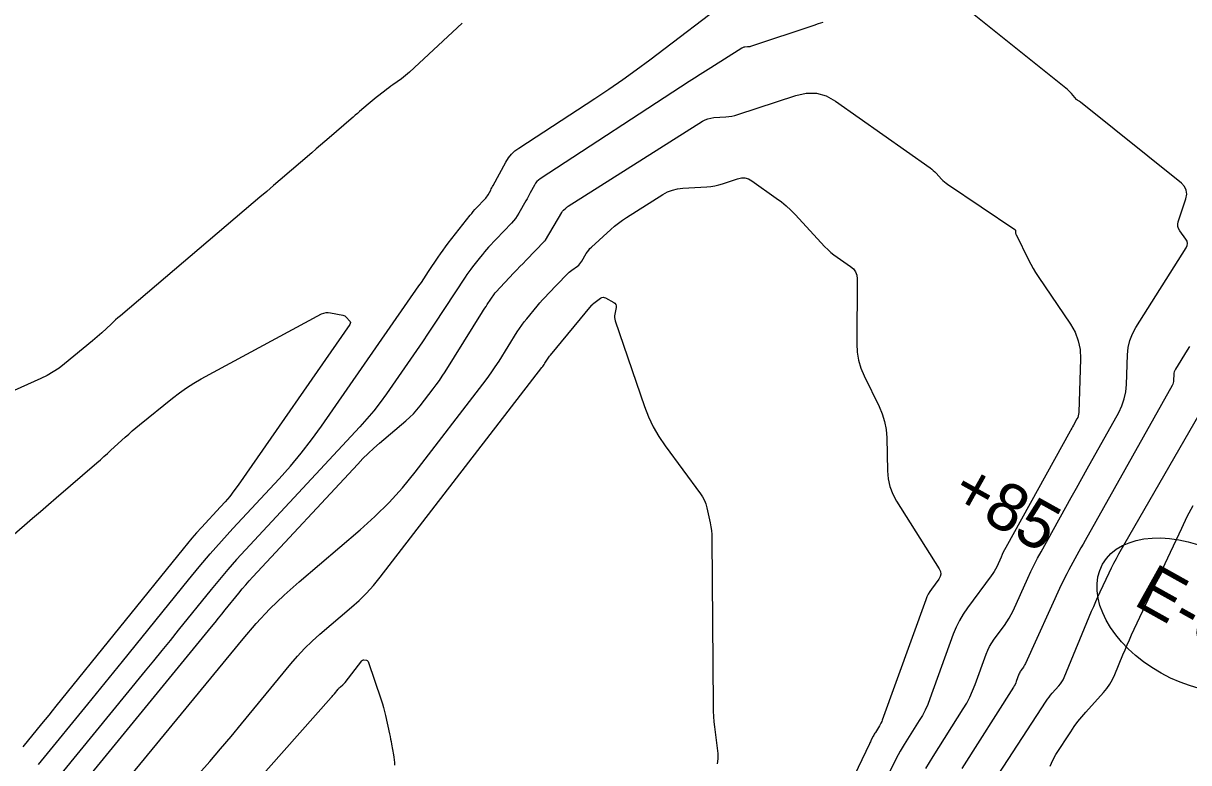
# Model space of a CAD drawing. Extents: x 1005228 to 1008882, y 1883389 to 1885754.
# Drawn here: x 1008141.6 to 1008294.8, y 1884868.6 to 1884965.9 of the extents above; entities that cross this region are included whole.
import ezdxf

# ---------------------------------------------------------------- set-up
doc = ezdxf.new("R2010")
doc.units = 0
for name, color, linetype in [('C-ANNO-NOTE', 7, 'Continuous'), ('R_Erosion', 7, 'Continuous'), ('S_BASELINE', 7, 'Continuous'), ('S_BRIDGE', 7, 'Continuous')]:
    doc.layers.add(name, color=color, linetype=linetype)

msp = doc.modelspace()

# ---------------------------------------------------------------- linework, layer by layer
at = {"layer": 'C-ANNO-NOTE'}
for points in [[(1008143.57, 1884868.4), (1008144, 1884868.89), (1008150.07, 1884876.31), (1008151.22, 1884877.72), (1008152.37, 1884879.13), (1008153.51, 1884880.54), (1008154.65, 1884881.95), (1008163.3, 1884892.66), (1008164.72, 1884894.38), (1008166.16, 1884896.08), (1008167.64, 1884897.76), (1008169.14, 1884899.4), (1008175.22, 1884905.95), (1008176.71, 1884907.61), (1008178.13, 1884909.32), (1008179.5, 1884911.07), (1008180.8, 1884912.88), (1008193.61, 1884931.32), (1008193.94, 1884931.79), (1008194.25, 1884932.26), (1008194.57, 1884932.73), (1008194.88, 1884933.2), (1008196.13, 1884935.09), (1008196.44, 1884935.56), (1008196.77, 1884936.03), (1008197.11, 1884936.48), (1008197.45, 1884936.93), (1008200.33, 1884940.61), (1008200.54, 1884940.86), (1008200.75, 1884941.11), (1008200.96, 1884941.35), (1008201.18, 1884941.59), (1008202.27, 1884942.73), (1008202.39, 1884942.86), (1008202.5, 1884943), (1008202.6, 1884943.15), (1008202.69, 1884943.3), (1008203.04, 1884943.92), (1008203.12, 1884944.07), (1008203.21, 1884944.23), (1008203.29, 1884944.38), (1008203.38, 1884944.54), (1008205.04, 1884947.61), (1008205.38, 1884948.15), (1008205.77, 1884948.64), (1008206.22, 1884949.07), (1008206.73, 1884949.45), (1008216.74, 1884955.98), (1008218.58, 1884957.21), (1008220.39, 1884958.46), (1008222.18, 1884959.75), (1008223.95, 1884961.07), (1008234.77, 1884969.32)], [(1008199.31, 1884965.87), (1008192.37, 1884959.44), (1008192.11, 1884959.21), (1008191.85, 1884958.99), (1008191.58, 1884958.77), (1008191.31, 1884958.57), (1008190.19, 1884957.77), (1008189.91, 1884957.57), (1008189.64, 1884957.36), (1008189.36, 1884957.15), (1008189.09, 1884956.95), (1008187.99, 1884956.09), (1008187.72, 1884955.87), (1008187.45, 1884955.66), (1008187.18, 1884955.44), (1008186.92, 1884955.21), (1008185.79, 1884954.24), (1008185.51, 1884954), (1008185.23, 1884953.76), (1008184.96, 1884953.52), (1008184.68, 1884953.28), (1008181.81, 1884950.81), (1008181.24, 1884950.32), (1008180.66, 1884949.83), (1008180.09, 1884949.34), (1008179.52, 1884948.84), (1008175.36, 1884945.27), (1008174.48, 1884944.51), (1008173.59, 1884943.75), (1008172.71, 1884942.99), (1008171.82, 1884942.24), (1008154.35, 1884927.39), (1008154.04, 1884927.12), (1008153.73, 1884926.85), (1008153.43, 1884926.58), (1008153.13, 1884926.3), (1008151.93, 1884925.17), (1008151.63, 1884924.89), (1008151.32, 1884924.62), (1008151.01, 1884924.35), (1008150.7, 1884924.09), (1008147.03, 1884921.08), (1008146.3, 1884920.51), (1008145.54, 1884920), (1008144.74, 1884919.55), (1008143.91, 1884919.14), (1008130.71, 1884913.22)], [(1008148.97, 1884865.29), (1008166.35, 1884886.51), (1008166.8, 1884887.06), (1008167.25, 1884887.61), (1008167.7, 1884888.16), (1008168.14, 1884888.71), (1008169.92, 1884890.92), (1008170.37, 1884891.47), (1008170.83, 1884892), (1008171.3, 1884892.54), (1008171.78, 1884893.06), (1008185.56, 1884907.89), (1008186.24, 1884908.61), (1008186.95, 1884909.3), (1008187.67, 1884909.97), (1008188.41, 1884910.63), (1008191.87, 1884913.57), (1008192.39, 1884914.04), (1008192.88, 1884914.52), (1008193.34, 1884915.03), (1008193.77, 1884915.57), (1008195.47, 1884917.77), (1008195.88, 1884918.32), (1008196.29, 1884918.88), (1008196.67, 1884919.46), (1008197.05, 1884920.04), (1008201.96, 1884927.89), (1008202.11, 1884928.13), (1008202.27, 1884928.38), (1008202.43, 1884928.62), (1008202.59, 1884928.87), (1008203.52, 1884930.28), (1008203.53, 1884930.3), (1008203.55, 1884930.32), (1008203.56, 1884930.34), (1008203.57, 1884930.36), (1008203.63, 1884930.44), (1008203.65, 1884930.46), (1008203.66, 1884930.48), (1008203.68, 1884930.49), (1008203.7, 1884930.51), (1008206.08, 1884933.02), (1008206.49, 1884933.44), (1008206.89, 1884933.86), (1008207.3, 1884934.28), (1008207.7, 1884934.71), (1008210.13, 1884937.22), (1008210.13, 1884937.23), (1008210.14, 1884937.24), (1008210.15, 1884937.25), (1008210.16, 1884937.26), (1008210.2, 1884937.29), (1008210.21, 1884937.29), (1008210.22, 1884937.3), (1008210.23, 1884937.31), (1008210.24, 1884937.32), (1008212.39, 1884940.99), (1008212.44, 1884941.07), (1008212.5, 1884941.15), (1008212.56, 1884941.22), (1008212.63, 1884941.29), (1008212.92, 1884941.55), (1008212.99, 1884941.62), (1008213.07, 1884941.68), (1008213.15, 1884941.73), (1008213.23, 1884941.79), (1008230.88, 1884952.97), (1008231.22, 1884953.16), (1008231.59, 1884953.3), (1008231.96, 1884953.4), (1008232.36, 1884953.45), (1008233.96, 1884953.54), (1008234.36, 1884953.58), (1008234.75, 1884953.64), (1008235.14, 1884953.73), (1008235.52, 1884953.84), (1008243.15, 1884956.38), (1008244.53, 1884956.68), (1008245.86, 1884956.65), (1008247.13, 1884956.3), (1008248.36, 1884955.61), (1008260.82, 1884946.83), (1008261.03, 1884946.67), (1008261.23, 1884946.51), (1008261.43, 1884946.33), (1008261.61, 1884946.14), (1008262.32, 1884945.37), (1008262.5, 1884945.18), (1008262.7, 1884945.01), (1008262.9, 1884944.84), (1008263.11, 1884944.69), (1008271.95, 1884938.73), (1008271.99, 1884938.69), (1008272.03, 1884938.65), (1008272.04, 1884938.6), (1008272.05, 1884938.54), (1008272.05, 1884938.3), (1008272.05, 1884938.24), (1008272.06, 1884938.18), (1008272.08, 1884938.12), (1008272.1, 1884938.07), (1008273.74, 1884934.74), (1008274.03, 1884934.17), (1008274.34, 1884933.62), (1008274.67, 1884933.07), (1008275.02, 1884932.54), (1008279.25, 1884926.3), (1008279.86, 1884925.24), (1008280.28, 1884924.12), (1008280.52, 1884922.95), (1008280.57, 1884921.73), (1008280.35, 1884914.68), (1008280.33, 1884914.45), (1008280.28, 1884914.24), (1008280.21, 1884914.02), (1008280.11, 1884913.82), (1008279.66, 1884913.02), (1008279.54, 1884912.81), (1008279.43, 1884912.61), (1008279.32, 1884912.41), (1008279.21, 1884912.21), (1008270.76, 1884896.91), (1008270.59, 1884896.6), (1008270.43, 1884896.29), (1008270.28, 1884895.98), (1008270.13, 1884895.67), (1008269.56, 1884894.4), (1008269.4, 1884894.09), (1008269.24, 1884893.78), (1008269.05, 1884893.49), (1008268.85, 1884893.21), (1008265.71, 1884888.98), (1008265.15, 1884888.16), (1008264.66, 1884887.31), (1008264.22, 1884886.43), (1008263.85, 1884885.51), (1008260.78, 1884877.01), (1008260.49, 1884876.27), (1008260.17, 1884875.55), (1008259.8, 1884874.85), (1008259.39, 1884874.17), (1008257.4, 1884871.03), (1008257.12, 1884870.58), (1008256.85, 1884870.12), (1008256.6, 1884869.66), (1008256.36, 1884869.18), (1008255.41, 1884867.29)], [(1008153.68, 1884864.44), (1008170.51, 1884884.93), (1008172.22, 1884886.93), (1008174.02, 1884888.84), (1008175.9, 1884890.67), (1008177.86, 1884892.41), (1008185.87, 1884899.24), (1008187.82, 1884900.99), (1008189.68, 1884902.84), (1008191.43, 1884904.78), (1008193.09, 1884906.82), (1008202.01, 1884918.39), (1008202.57, 1884919.13), (1008203.11, 1884919.89), (1008203.63, 1884920.66), (1008204.14, 1884921.44), (1008206.53, 1884925.27), (1008206.82, 1884925.72), (1008207.13, 1884926.16), (1008207.45, 1884926.59), (1008207.79, 1884927.01), (1008209.17, 1884928.67), (1008209.51, 1884929.08), (1008209.87, 1884929.49), (1008210.23, 1884929.89), (1008210.6, 1884930.28), (1008213.03, 1884932.8), (1008213.19, 1884932.96), (1008213.36, 1884933.11), (1008213.53, 1884933.26), (1008213.71, 1884933.39), (1008214.44, 1884933.93), (1008214.61, 1884934.07), (1008214.76, 1884934.22), (1008214.9, 1884934.39), (1008215.03, 1884934.58), (1008215.61, 1884935.59), (1008215.76, 1884935.81), (1008215.92, 1884936.02), (1008216.09, 1884936.23), (1008216.28, 1884936.41), (1008218.82, 1884938.72), (1008219.32, 1884939.16), (1008219.83, 1884939.57), (1008220.36, 1884939.96), (1008220.91, 1884940.32), (1008225.68, 1884943.34), (1008226.29, 1884943.68), (1008226.93, 1884943.93), (1008227.59, 1884944.1), (1008228.28, 1884944.18), (1008231.46, 1884944.37), (1008231.98, 1884944.41), (1008232.5, 1884944.5), (1008233.01, 1884944.61), (1008233.51, 1884944.76), (1008235.5, 1884945.42), (1008235.99, 1884945.53), (1008236.46, 1884945.52), (1008236.92, 1884945.39), (1008237.36, 1884945.15), (1008240.58, 1884942.87), (1008241.25, 1884942.38), (1008241.89, 1884941.85), (1008242.5, 1884941.29), (1008243.08, 1884940.69), (1008246.97, 1884936.47), (1008247.34, 1884936.09), (1008247.74, 1884935.73), (1008248.15, 1884935.4), (1008248.58, 1884935.09), (1008250.35, 1884933.89), (1008250.73, 1884933.57), (1008251.01, 1884933.18), (1008251.17, 1884932.74), (1008251.22, 1884932.23), (1008251.16, 1884923.71), (1008251.21, 1884922.61), (1008251.39, 1884921.55), (1008251.69, 1884920.51), (1008252.12, 1884919.5), (1008254.1, 1884915.47), (1008254.52, 1884914.48), (1008254.83, 1884913.47), (1008255.02, 1884912.42), (1008255.1, 1884911.35), (1008255.21, 1884907.01), (1008255.3, 1884905.95), (1008255.53, 1884904.93), (1008255.9, 1884903.95), (1008256.41, 1884903.01), (1008262.01, 1884894.1), (1008262.17, 1884893.76), (1008262.21, 1884893.43), (1008262.14, 1884893.09), (1008261.95, 1884892.76), (1008260.99, 1884891.46), (1008260.76, 1884891.13), (1008260.55, 1884890.78), (1008260.38, 1884890.42), (1008260.23, 1884890.04), (1008254.51, 1884874.21), (1008254.44, 1884874.02), (1008254.35, 1884873.82), (1008254.25, 1884873.63), (1008254.14, 1884873.45), (1008253.61, 1884872.61), (1008253.53, 1884872.49), (1008253.46, 1884872.37), (1008253.39, 1884872.24), (1008253.33, 1884872.12), (1008253.07, 1884871.61), (1008253.01, 1884871.48), (1008252.95, 1884871.35), (1008252.89, 1884871.22), (1008252.83, 1884871.1), (1008248.34, 1884861.67)], [(1008164.69, 1884867.18), (1008166.11, 1884868.8), (1008167.52, 1884870.43), (1008168.91, 1884872.08), (1008170.28, 1884873.74), (1008176.76, 1884881.62), (1008177.65, 1884882.65), (1008178.58, 1884883.65), (1008179.56, 1884884.6), (1008180.58, 1884885.51), (1008184.74, 1884889.06), (1008185.76, 1884889.97), (1008186.72, 1884890.93), (1008187.64, 1884891.94), (1008188.5, 1884893), (1008209.78, 1884920.6), (1008209.88, 1884920.73), (1008209.97, 1884920.86), (1008210.06, 1884921), (1008210.15, 1884921.14), (1008210.5, 1884921.69), (1008210.59, 1884921.82), (1008210.68, 1884921.96), (1008210.78, 1884922.09), (1008210.88, 1884922.21), (1008216.31, 1884928.76), (1008216.33, 1884928.78), (1008216.36, 1884928.81), (1008216.38, 1884928.84), (1008216.4, 1884928.86), (1008216.5, 1884928.96), (1008216.53, 1884928.99), (1008216.55, 1884929.01), (1008216.58, 1884929.04), (1008216.61, 1884929.06), (1008217.49, 1884929.7), (1008217.65, 1884929.79), (1008217.81, 1884929.83), (1008217.97, 1884929.81), (1008218.14, 1884929.75), (1008219.21, 1884929.16), (1008219.38, 1884929.03), (1008219.49, 1884928.88), (1008219.54, 1884928.7), (1008219.52, 1884928.49), (1008219.35, 1884927.6), (1008219.32, 1884927.38), (1008219.32, 1884927.16), (1008219.35, 1884926.94), (1008219.41, 1884926.73), (1008223.27, 1884915.48), (1008223.8, 1884914.11), (1008224.42, 1884912.79), (1008225.15, 1884911.52), (1008225.98, 1884910.31), (1008230.62, 1884903.99), (1008230.9, 1884903.57), (1008231.13, 1884903.12), (1008231.31, 1884902.65), (1008231.45, 1884902.16), (1008231.9, 1884900.15), (1008232, 1884899.65), (1008232.07, 1884899.14), (1008232.11, 1884898.63), (1008232.13, 1884898.12), (1008232.27, 1884876.12), (1008232.29, 1884875.41), (1008232.32, 1884874.71), (1008232.38, 1884874.01), (1008232.46, 1884873.32), (1008232.83, 1884870.53), (1008232.89, 1884869.84), (1008232.88, 1884869.14), (1008232.8, 1884868.46)], [(1008125.71, 1884885.97), (1008141.76, 1884899.86), (1008142.8, 1884900.76), (1008143.85, 1884901.67), (1008144.89, 1884902.57), (1008145.93, 1884903.47), (1008151.24, 1884908.04), (1008151.72, 1884908.45), (1008152.19, 1884908.87), (1008152.66, 1884909.29), (1008153.12, 1884909.72), (1008154.98, 1884911.42), (1008155.45, 1884911.84), (1008155.92, 1884912.26), (1008156.4, 1884912.66), (1008156.89, 1884913.06), (1008161.21, 1884916.57), (1008162.11, 1884917.26), (1008163.04, 1884917.91), (1008164, 1884918.52), (1008164.98, 1884919.08), (1008180.81, 1884927.63), (1008181.1, 1884927.75), (1008181.39, 1884927.82), (1008181.69, 1884927.84), (1008182, 1884927.8), (1008183.58, 1884927.47), (1008183.72, 1884927.43), (1008183.85, 1884927.37), (1008183.97, 1884927.29), (1008184.08, 1884927.18), (1008184.49, 1884926.74), (1008184.56, 1884926.62), (1008184.6, 1884926.51), (1008184.58, 1884926.39), (1008184.52, 1884926.26), (1008169.83, 1884905.12), (1008169.29, 1884904.37), (1008168.73, 1884903.64), (1008168.13, 1884902.94), (1008167.52, 1884902.25), (1008165.01, 1884899.54), (1008164.38, 1884898.86), (1008163.77, 1884898.17), (1008163.17, 1884897.47), (1008162.59, 1884896.75), (1008145.87, 1884876.04), (1008145.4, 1884875.46), (1008144.93, 1884874.88), (1008144.46, 1884874.31), (1008143.99, 1884873.73), (1008141.51, 1884870.7)], [(1008294.91, 1884923.34), (1008294.62, 1884922.86), (1008293.05, 1884920.36), (1008292.96, 1884920.2), (1008292.89, 1884920.03), (1008292.85, 1884919.86), (1008292.84, 1884919.67), (1008292.81, 1884918.93), (1008292.8, 1884918.75), (1008292.76, 1884918.57), (1008292.7, 1884918.4), (1008292.62, 1884918.24), (1008281.18, 1884897.83), (1008280.91, 1884897.35), (1008280.64, 1884896.87), (1008280.37, 1884896.39), (1008280.1, 1884895.9), (1008279.03, 1884893.97), (1008278.77, 1884893.48), (1008278.52, 1884892.99), (1008278.28, 1884892.5), (1008278.04, 1884892), (1008273.34, 1884881.66), (1008273.28, 1884881.53), (1008273.22, 1884881.41), (1008273.15, 1884881.3), (1008273.07, 1884881.19), (1008272.74, 1884880.75), (1008272.67, 1884880.64), (1008272.6, 1884880.52), (1008272.54, 1884880.4), (1008272.49, 1884880.28), (1008272.14, 1884879.31), (1008272.06, 1884879.11), (1008271.97, 1884878.92), (1008271.87, 1884878.73), (1008271.76, 1884878.54), (1008264.98, 1884867.86)], [(1008269.17, 1884866.14), (1008276.07, 1884876.71), (1008276.25, 1884876.98), (1008276.45, 1884877.25), (1008276.65, 1884877.5), (1008276.87, 1884877.75), (1008277.75, 1884878.74), (1008277.96, 1884878.99), (1008278.14, 1884879.26), (1008278.31, 1884879.54), (1008278.44, 1884879.84), (1008282.04, 1884888.54), (1008282.31, 1884889.18), (1008282.59, 1884889.82), (1008282.87, 1884890.45), (1008283.16, 1884891.08), (1008284.34, 1884893.6), (1008284.65, 1884894.23), (1008284.96, 1884894.85), (1008285.29, 1884895.46), (1008285.63, 1884896.07), (1008296.29, 1884914.61)], [(1008276.58, 1884868.19), (1008276.92, 1884868.96), (1008277.35, 1884869.71), (1008279.3, 1884872.7), (1008279.76, 1884873.37), (1008280.24, 1884874.02), (1008280.75, 1884874.66), (1008281.28, 1884875.27), (1008283.59, 1884877.85), (1008284.04, 1884878.4), (1008284.44, 1884878.97), (1008284.78, 1884879.58), (1008285.08, 1884880.21), (1008286.16, 1884882.83), (1008286.43, 1884883.48), (1008286.72, 1884884.13), (1008287.01, 1884884.78), (1008287.3, 1884885.42), (1008293.9, 1884899.48), (1008294.62, 1884900.98), (1008295.37, 1884902.46)], [(1008153.57, 1884845.05), (1008182.07, 1884877.19), (1008182.18, 1884877.32), (1008182.29, 1884877.44), (1008182.39, 1884877.57), (1008182.5, 1884877.7), (1008183, 1884878.3), (1008183.07, 1884878.38), (1008183.14, 1884878.46), (1008183.21, 1884878.53), (1008183.29, 1884878.6), (1008183.61, 1884878.88), (1008183.69, 1884878.95), (1008183.77, 1884879.02), (1008183.84, 1884879.1), (1008183.9, 1884879.18), (1008186.08, 1884882.01), (1008186.14, 1884882.07), (1008186.21, 1884882.11), (1008186.28, 1884882.13), (1008186.36, 1884882.13), (1008186.7, 1884882.09), (1008186.78, 1884882.07), (1008186.85, 1884882.04), (1008186.9, 1884881.98), (1008186.93, 1884881.91), (1008188.63, 1884876.89), (1008188.8, 1884876.38), (1008188.95, 1884875.87), (1008189.08, 1884875.36), (1008189.2, 1884874.85), (1008189.74, 1884872.42), (1008189.81, 1884872.08), (1008189.88, 1884871.74), (1008189.95, 1884871.39), (1008190.01, 1884871.05), (1008190.26, 1884869.68), (1008190.31, 1884869.34), (1008190.36, 1884868.99), (1008190.39, 1884868.65), (1008190.41, 1884868.3)]]:
    msp.add_lwpolyline(points, dxfattribs=at)
at = {"layer": 'R_Erosion'}
msp.add_ellipse((1008295.44, 1884888.04), major_axis=(11.96, -6.68), ratio=0.638788, dxfattribs=at)
at = {"layer": 'S_BRIDGE'}
for points in [[(1008260.25, 1884867.87), (1008260.71, 1884868.66), (1008261.19, 1884869.45), (1008265.16, 1884875.69), (1008265.62, 1884876.46), (1008266.03, 1884877.25), (1008266.4, 1884878.06), (1008266.73, 1884878.9), (1008268.17, 1884882.9), (1008268.38, 1884883.42), (1008268.63, 1884883.92), (1008268.91, 1884884.4), (1008269.23, 1884884.87), (1008270.58, 1884886.68), (1008270.9, 1884887.14), (1008271.2, 1884887.62), (1008271.47, 1884888.11), (1008271.72, 1884888.61), (1008273.66, 1884892.88), (1008274.07, 1884893.76), (1008274.49, 1884894.63), (1008274.94, 1884895.5), (1008275.4, 1884896.35), (1008278.64, 1884902.22), (1008279.34, 1884903.48), (1008280.04, 1884904.74), (1008280.74, 1884906), (1008281.44, 1884907.25), (1008285.61, 1884914.69), (1008286.03, 1884915.56), (1008286.34, 1884916.45), (1008286.54, 1884917.38), (1008286.63, 1884918.34), (1008286.75, 1884922.25), (1008286.85, 1884923.21), (1008287.06, 1884924.13), (1008287.4, 1884925.01), (1008287.86, 1884925.85), (1008294.46, 1884936.34), (1008294.6, 1884936.63), (1008294.63, 1884936.91), (1008294.58, 1884937.19), (1008294.42, 1884937.47), (1008293.63, 1884938.56), (1008293.46, 1884938.85), (1008293.38, 1884939.14), (1008293.37, 1884939.44), (1008293.44, 1884939.76), (1008294.44, 1884942.79), (1008294.55, 1884943.37), (1008294.49, 1884943.91), (1008294.25, 1884944.39), (1008293.84, 1884944.82), (1008280.58, 1884955.49), (1008280.54, 1884955.53), (1008280.5, 1884955.56), (1008280.45, 1884955.59), (1008280.41, 1884955.61), (1008280.22, 1884955.71), (1008280.18, 1884955.74), (1008280.13, 1884955.77), (1008280.1, 1884955.81), (1008280.06, 1884955.85), (1008279.4, 1884956.62), (1008279.28, 1884956.76), (1008279.15, 1884956.89), (1008279.01, 1884957.01), (1008278.87, 1884957.13), (1008263.53, 1884969.46)], [(1008246.7, 1884965.96), (1008246.11, 1884965.77), (1008245.53, 1884965.58), (1008237.19, 1884962.81), (1008237.1, 1884962.78), (1008237.01, 1884962.76), (1008236.91, 1884962.74), (1008236.82, 1884962.74), (1008236.43, 1884962.71), (1008236.34, 1884962.7), (1008236.24, 1884962.68), (1008236.16, 1884962.64), (1008236.07, 1884962.6), (1008231.98, 1884960), (1008231.27, 1884959.55), (1008230.56, 1884959.1), (1008229.85, 1884958.64), (1008229.15, 1884958.18), (1008209.56, 1884945.39), (1008209.33, 1884945.22), (1008209.12, 1884945.03), (1008208.95, 1884944.81), (1008208.8, 1884944.56), (1008208.24, 1884943.54), (1008208.1, 1884943.29), (1008207.96, 1884943.03), (1008207.82, 1884942.78), (1008207.68, 1884942.52), (1008206.75, 1884940.87), (1008206.54, 1884940.52), (1008206.31, 1884940.18), (1008206.05, 1884939.86), (1008205.78, 1884939.56), (1008202.77, 1884936.4), (1008202.49, 1884936.09), (1008202.21, 1884935.78), (1008201.95, 1884935.47), (1008201.69, 1884935.14), (1008200.66, 1884933.84), (1008200.41, 1884933.51), (1008200.16, 1884933.17), (1008199.92, 1884932.83), (1008199.69, 1884932.49), (1008195.6, 1884926.27), (1008194.84, 1884925.12), (1008194.07, 1884923.98), (1008193.3, 1884922.84), (1008192.51, 1884921.7), (1008189.33, 1884917.12), (1008188.51, 1884915.99), (1008187.66, 1884914.89), (1008186.77, 1884913.83), (1008185.85, 1884912.79), (1008170.8, 1884896.6), (1008169.64, 1884895.33), (1008168.5, 1884894.04), (1008167.39, 1884892.73), (1008166.3, 1884891.4), (1008161.97, 1884886.04), (1008160.89, 1884884.71), (1008159.81, 1884883.37), (1008158.72, 1884882.04), (1008157.63, 1884880.7), (1008146.48, 1884867.09)]]:
    msp.add_lwpolyline(points, dxfattribs=at)

# ---------------------------------------------------------------- texts
at = {"layer": 'R_Erosion'}
msp.add_text('E-6', height=6.25, rotation=330.815, dxfattribs=at).set_placement((1008287.37, 1884889.49))
at = {"layer": 'S_BASELINE'}
msp.add_text('+85', height=6.25, rotation=330.815, dxfattribs=at).set_placement((1008263.18, 1884903.01))

doc.saveas('drawing.dxf')
